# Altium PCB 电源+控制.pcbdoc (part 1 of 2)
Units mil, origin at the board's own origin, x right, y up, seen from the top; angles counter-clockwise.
Board outline 7045 x 4395 mil, 2 copper layers (Top Layer, Bottom Layer); 84 components, 54 nets, 254 pads, 98 vias.
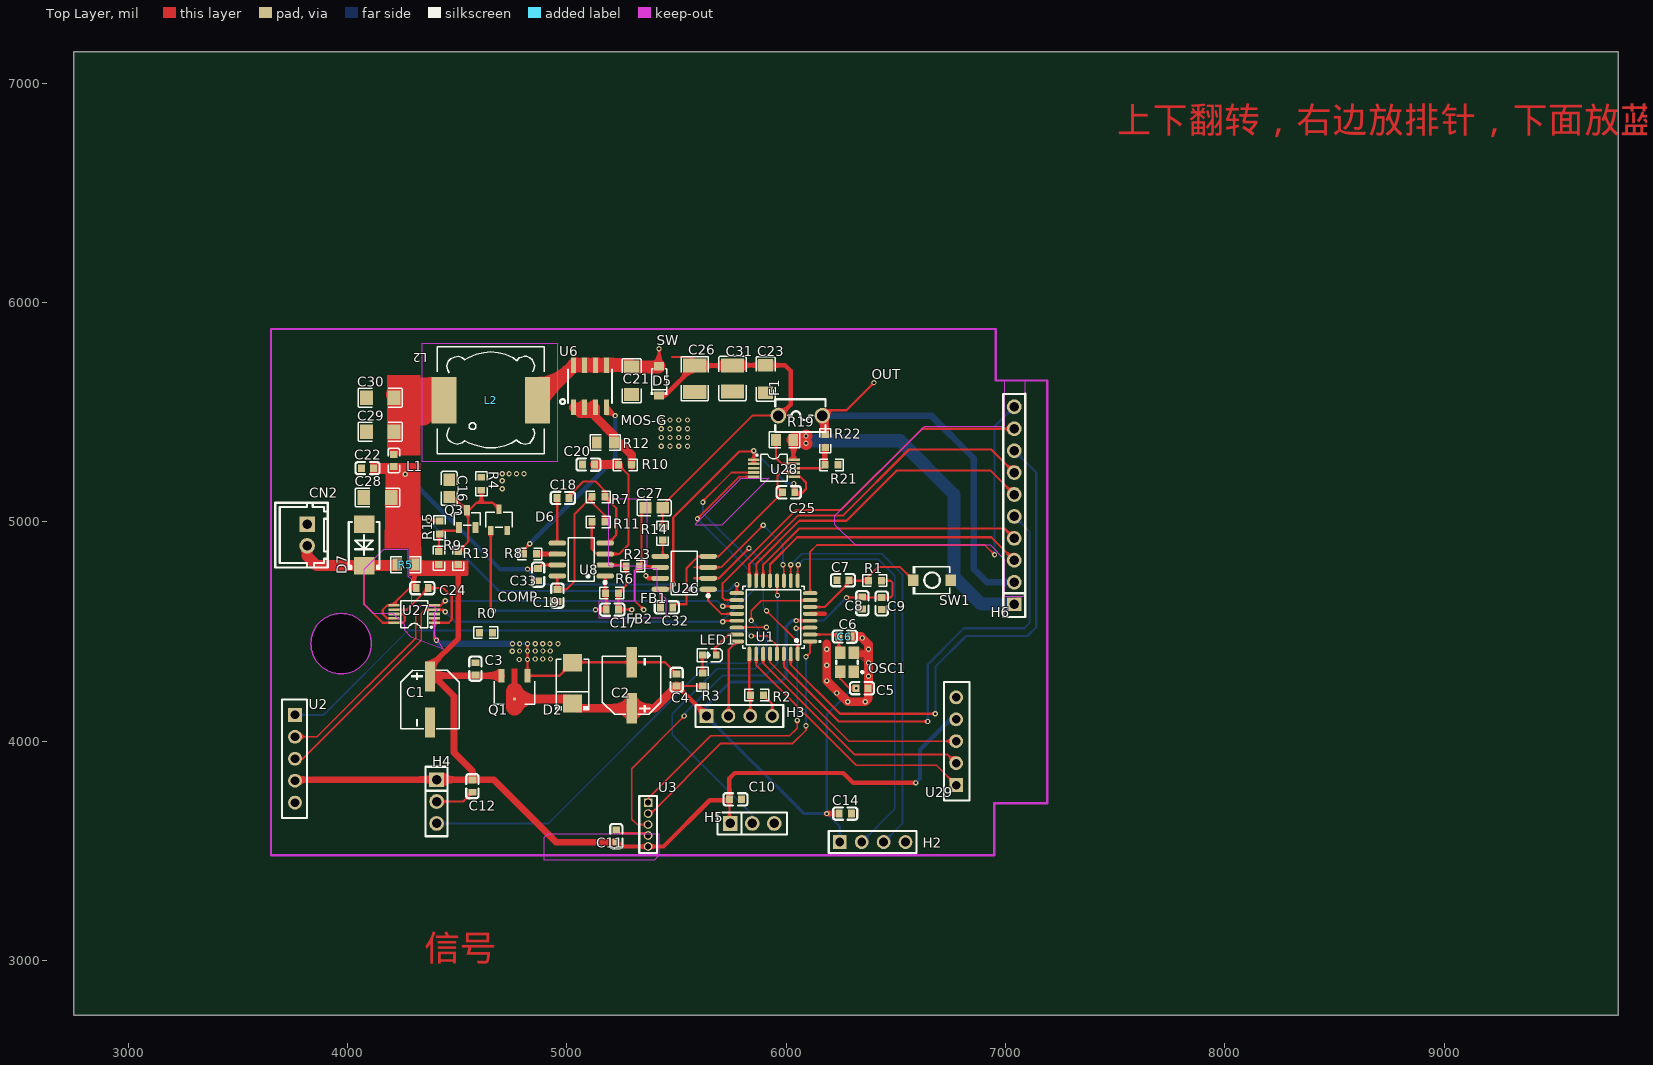
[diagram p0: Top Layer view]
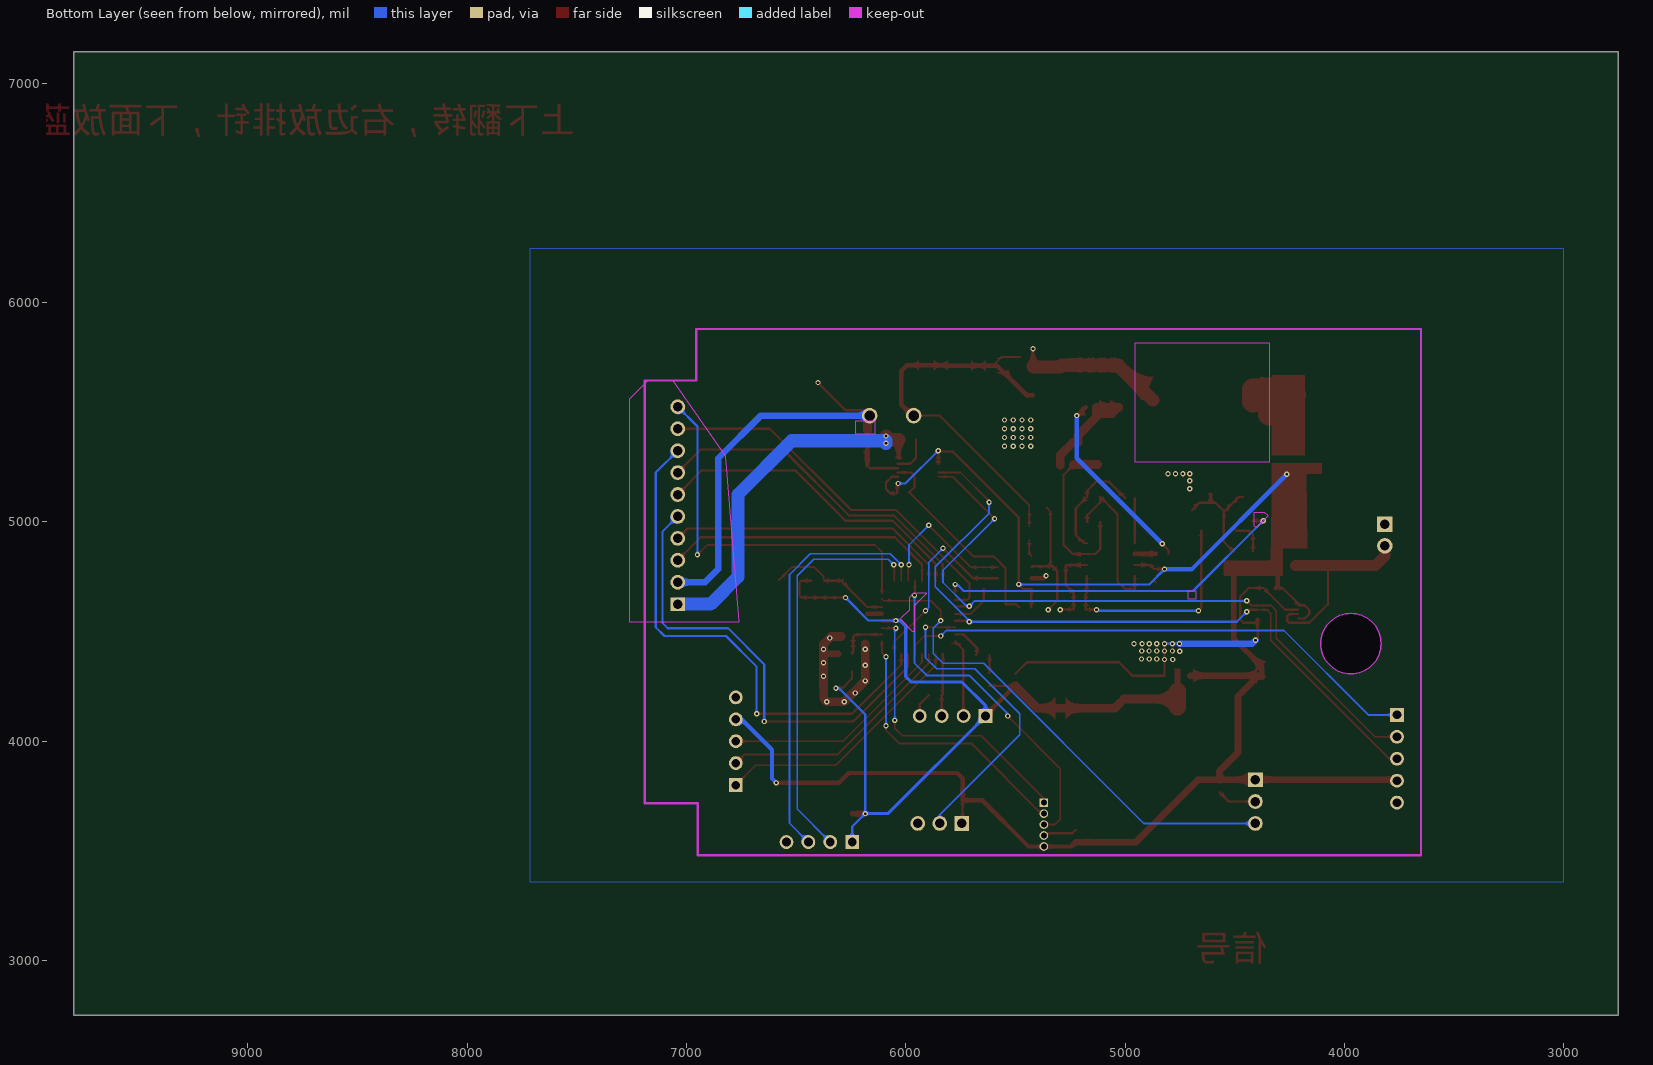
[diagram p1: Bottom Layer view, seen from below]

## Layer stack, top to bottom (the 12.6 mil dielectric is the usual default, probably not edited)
Top Layer: signal copper (thickness not stored)
Dielectric: dielectric 12.6, FR-4, Dk 4.8
Bottom Layer: signal copper (thickness not stored)

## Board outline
9795,2750 2750,2750 2750,7145 9795,7145
cut-out: 4107.8,4445 cw(c3970,4445) 3832.2,4445 cw(c3970,4445)

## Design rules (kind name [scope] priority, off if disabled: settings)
BoardOutlineClearance copperThickness1oz [All] p0: genericclearance=10 ignorepadtopadclearanceinfootprint=FALSE except(0: Arc-SplitContinuation Track-SplitContinuation SMDPad-SplitContinuation THPad-SplitContinuation Via-SplitContinuation Fill-SplitContinuation Poly-SplitContinuation Region-SplitContinuation Text-SplitContinuation; 6: SMDPad-CutoutEdge THPad-CutoutEdge Via-CutoutEdge Fill-CutoutEdge Region-CutoutEdge; 11.8: Track-OutlineEdge SMDPad-OutlineEdge THPad-OutlineEdge Via-OutlineEdge Fill-OutlineEdge Region-OutlineEdge Poly-OutlineEdge Text-OutlineEdge Track-CutoutEdge)
BoardOutlineClearance copperThickness2oz [All] p0: genericclearance=10 ignorepadtopadclearanceinfootprint=FALSE except(0: Arc-SplitContinuation Track-SplitContinuation SMDPad-SplitContinuation THPad-SplitContinuation Via-SplitContinuation Fill-SplitContinuation Poly-SplitContinuation Region-SplitContinuation Text-SplitContinuation; 6: SMDPad-CutoutEdge THPad-CutoutEdge Via-CutoutEdge Fill-CutoutEdge Region-CutoutEdge; 11.8: Track-OutlineEdge SMDPad-OutlineEdge THPad-OutlineEdge Via-OutlineEdge Fill-OutlineEdge Region-OutlineEdge Poly-OutlineEdge Text-OutlineEdge Track-CutoutEdge)
Clearance copperThickness1oz [(InNet('GND') OR InNet('+5V') OR InNet('+3.3V') OR InNet('RADER_RX') OR InNet('OSC_IN') OR InNet('RADER') OR InNet('NRST') OR InNet('LIGHT_ADC') OR InNet('SWITCH6') OR InNet('BLE_TX') OR InNet('BLE_RX') OR InNet('SPI_MOSI') OR InNet('RADER_TX') OR InNet('SWITCH1') OR InNet('SWITCH2') OR InNet('SWITCH4') OR InNet('POWER') OR InNet('SWITCH5') OR InNet('I2C1_SCL') OR InNet('SPI_CS') OR InNet('I2C1_SDA') OR InNet('INFRARED-RAY') OR InNet('LED') OR InNet('SWDIO') OR InNet('SWCLK') OR InNet('CLK') OR InNet('CS') OR InNet('MOSI') OR InNet('DS3231') OR InNet('COLON1') OR InNet('COLON2') OR InNet('$1N3438') OR InNet('$3N2641') OR InNet('$3N2640') OR InNet('VBUS') OR InNet('170_GND') OR InNet('$3N2623') OR InNet('$3N2617') OR InNet('$3N2620') OR InNet('170V') OR InNet('$3N2630') OR InNet('$3N2637') OR InNet('$3N2628') OR InNet('$3N2629') OR InNet('$3N2638') OR InNet('$3N2615') OR InNet('$3N2625') OR InNet('$3N2624') OR InNet('$3N2608') OR InNet('$3N2618') OR InNet('17V') OR InNet('SWITCH3') OR InNet('PGND') OR InNet('SPI_SCK'))] p1: gap=7 ignorepadtopadclearanceinfootprint=FALSE except(4: Track-Track; 6: Track-SMDPad SMDPad-SMDPad Track-THPad SMDPad-THPad THPad-THPad Track-Via SMDPad-Via THPad-Via Via-Via Track-Fill SMDPad-Fill THPad-Fill Via-Fill Fill-Fill SMDPad-Region THPad-Region Via-Region Fill-Region Region-Region Track-Poly SMDPad-Poly THPad-Poly Via-Poly Fill-Poly Poly-Poly Track-Text SMDPad-Text THPad-Text Via-Text Fill-Text Region-Text Poly-Text Text-Text Track-Hole SMDPad-Hole THPad-Hole Via-Hole Fill-Hole Region-Hole Poly-Hole Text-Hole; 11.8: Track-Region Region-Poly Track-Sheet SMDPad-Sheet THPad-Sheet Via-Sheet Fill-Sheet Region-Sheet Poly-Sheet Text-Sheet Sheet-Hole)
Clearance copperThickness2oz [All] p1: gap=7 ignorepadtopadclearanceinfootprint=FALSE except(6: Track-SMDPad SMDPad-SMDPad Track-THPad SMDPad-THPad THPad-THPad Track-Via SMDPad-Via THPad-Via Via-Via Track-Fill SMDPad-Fill THPad-Fill Via-Fill Fill-Fill SMDPad-Region THPad-Region Via-Region Fill-Region Region-Region Track-Poly SMDPad-Poly THPad-Poly Via-Poly Fill-Poly Poly-Poly Track-Text SMDPad-Text THPad-Text Via-Text Fill-Text Region-Text Poly-Text Text-Text Track-Hole SMDPad-Hole THPad-Hole Via-Hole Fill-Hole Region-Hole Poly-Hole Text-Hole; 8: Track-Track; 11.8: Track-Region Region-Poly Track-Sheet SMDPad-Sheet THPad-Sheet Via-Sheet Fill-Sheet Region-Sheet Poly-Sheet Text-Sheet Sheet-Hole)
DiffPairsRouting differentialPair [All] p1: maxuncoupledlength=10 minlimit=6 maxlimit=6 mostfreqgap=6 toplayer_minwidth=5 toplayer_prefwidth=10 toplayer_maxwidth=100 bottomlayer_minwidth=5 bottomlayer_prefwidth=10 bottomlayer_maxwidth=100
PasteMaskExpansion pasteMaskExpansion [All] p1: expansion=0
PlaneConnect innerPlane [All] p1: planeconnectstyle=Relief reliefexpansion=20 reliefentries=4 reliefconductorwidth=10 reliefairgap=10
PolygonConnect copperRegion [All] p1: connectstyle=Relief reliefentries=4 reliefconductorwidth=10 polygonreliefangle="90 Angle" airgapwidth=10
RoutingVias viaSize [All] p1: viastyle="Through Hole" holewidth=12.0078 minholewidth=11.811 maxholewidth=248.0314 width=24.0158 minwidth=19.685 maxwidth=393.7008
SolderMaskExpansion solderMaskExpansion [All] p1: useseparateexpansions=TRUE expansion=2 expansionbottom=2
Width copperThickness1oz [All] p1: maxlimit=100 minlimit=5 preferedwidth=10
Width copperThickness2oz [All] p1: maxlimit=100 minlimit=8 preferedwidth=10

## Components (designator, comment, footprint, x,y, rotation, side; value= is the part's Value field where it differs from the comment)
C1 "RVT220UF10V67RV0037" CAP-SMD_BD6.3-L6.6-W6.6-FD 4375.55,4190 r270 top
C2 "RVT220UF10V67RV0037" CAP-SMD_BD6.3-L6.6-W6.6-FD 5295,4255.09 r90 top
C3 "CC0603KRX7R9BB104" c0603 4582.4,4330.4 r270 top
C4 "CC0603KRX7R9BB104" c0603 5500,4279.79 r270 top
C5 "CC0603KRX7R9BB104" c0603 6346.07,4241.5 r0 top
C6 "CC0603KRX7R9BB104" c0603 6267.31,4477.36 r0 top
C7 "CC0603KRX7R9BB104" c0603 6259.45,4734.1 r0 top
C8 "CC0603KRX7R9BB104" c0603 6346.97,4630 r90 top
C9 "CC0603KRX7R9BB104" c0603 6435.52,4628.44 r90 top
C10 "CC0603KRX7R9BB104" c0603 5768.23,3735 r180 top
C11 "CC0603KRX7R9BB104" c0603 5225,3567.56 r90 top
C12 "CC0603KRX7R9BB104" c0603 4568.73,3794.87 r90 top
C14 "CC0603KRX7R9BB104" c0603 6269.31,3670 r0 top
C16 "CC0805KRX7R9BB104" C0805 4463.04,5152.79 r270 top
C17 "CC0805KRX7R9BB104" c0603 5206.66,4600.41 r180 top
C18 "CC0805KRX7R9BB104" c0603 4981.5,5109.05 r0 top
C19 "CC0805KRX7R9BB104" c0603 4956.38,4664.37 r90 top
C20 "CC0805KRX7R9BB104" c0603 5098.5,5261.61 r0 top
C21 "CC0805KRX7R9BB104" c1206 5295,5643.76 r90 top
C22 "CC0805KRX7R9BB104" c0603 4090.86,5245 r0 top
C23 "CC0805KRX7R9BB104" c1206 5905.99,5651.75 r90 top
C24 "0.1u" c0603 4340.12,4698.19 r180 top
C25 "0.1u" c0603 6011.25,5135 r0 top
C26 "CC0805KRX7R9BB104" c1210 5582.58,5653.03 r90 top
C27 "CC0805KRX7R9BB104" C0805 5397.23,5064.76 r0 top
C28 "CC0805KRX7R9BB104" c1206 4136.14,5111.28 r0 top
C29 "CC0805KRX7R9BB104" c1206 4148.36,5411.28 r0 top
C30 "CC0805KRX7R9BB104" c1206 4148.36,5566.28 r0 top
C31 "CC0805KRX7R9BB104" c1210 5754.88,5653.91 r90 top
C32 "CC0805KRX7R9BB104" c0603 5455,4610.21 r180 top
C33 "CAP_0603" c0603 4868.3,4759.22 r270 top
CN2 "ZX-XH2.54-2PZZ" CONN-TH_2P-P2.50_HX25003-2A 3815,4940 r270 top
COMP "Test-Point" Test-Point-0.5mm 4665.69,4595.29 r0 top
D2 "SMBJ3.3A_C362089" SMB_L4.6-W3.6-LS5.3-RD 5025,4264.72 r90 top
D5 "ES1J_C691230" sod-123_l2.7-w1.6-ls3.6-rd 5420,5643.76 r90 top
D6 "BAT54C,215" SOT-23-3_L2.9-W1.6-P1.90-LS2.8-BR 4690,5009.58 r270 top
D7 "SMBJ5.0A_C726811" SMB_L4.4-W3.6-LS5.3-RD 4075,4895.17 r90 top
F1 "JK250-080U" FUSE-TH_L5.8-W3.8-P5.10-D0.8 6064.4,5485 r0 top
FB1 "Test-Point" Test-Point-0.5mm 5346.22,4600.74 r0 top
FB2 "Test-Point" Test-Point-0.5mm 5297.87,4601.7 r0 top
H2 "排针" SIP-2.54MM-4P-CJT-H8.54 6394.12,3540 r180 top
H3 "排针" SIP-2.54MM-4P-CJT-H8.54 5786.08,4115 r180 top
H4 "PZ254V-11-03P" HDR-TH_3P-P2.54-V-M 4405.36,3725 r270 top
H5 "PZ254V-11-03P" HDR-TH_3P-P2.54-V-M 5845,3625 r0 top
H6 "MH254V-11-10-1196" HDR-TH_10P-P2.54-V-M 7040,5075 r90 top
L1 "PZ3216D101-3R0TF" l0603 4211.06,5280 r90 top
L2 "CXP0630-330M-AG(33uh)" 33uh功率电感 4652.23,5555 r180 top
LED1 "NCD0603R1_C84263" LED0603-RD_RED 5649.3,4392.7 r180 top
MOS-G "Test-Point" Test-Point-0.5mm 5220.34,5484.01 r0 top
OSC1 "OT2EL4C4JI-111OLP-8M" OSC-SMD_4P-L3.2-W2.5-BL-1 6277.13,4360.27 r90 top
OUT "Test-Point" Test-Point-0.5mm 6400.07,5635.31 r0 top
Q1 "AMS1117-3.3V_C5120796" SOT-89-3_L4.5-W2.5-P1.50-LS4.2-BR 4760.78,4245.58 r90 top
Q3 "MMBT5551_C2145" SOT-23-3_L2.9-W1.3-P1.90-LS2.4-BR 4545,5013.67 r270 top
R0 "Res_0603" r0603 4630,4495.1 r0 top
R1 "0805W8F1002T5E_C17414" r0603 6404.02,4732.01 r0 top
R2 "0805W8F1002T5E_C17414" r0603 5865.74,4210 r180 top
R3 "0805W8F1002T5E_C17414" r0603 5618.82,4282.01 r90 top
R4 "0805W8F1002T5E_C17414" r0603 4609.8,5174.08 r270 top
R5 "10mΩ" R0805 4265,4805.25 r180 top
R6 "0805W8F1002T5E_C17414" r0603 5204.43,4675.24 r180 top
R7 "0805W8F1002T5E_C17414" r0603 5143.03,5114.29 r180 top
R8 "0805W8F1002T5E_C17414" r0603 4831.07,4854.37 r0 top
R9 "0805W8F1002T5E_C17414" r0603 4416.26,4834.91 r270 top
R10 "0805W8F1002T5E_C17414" r0603 5265.34,5260 r180 top
R11 "0805W8F1002T5E_C17414" r0603 5143.03,5000.02 r0 top
R12 "RL10FTNR160" R0805 5174.73,5362.41 r0 top
R13 "0805W8F1002T5E_C17414" r0603 4504.37,4834.91 r270 top
R14 "0805W8F1002T5E_C17414" r0603 5436.6,4948.08 r90 top
R15 "0805W8F1002T5E_C17414" r0603 4419.46,4973.68 r90 top
R19 "100mΩ" R0805 5992.89,5374.48 r0 top
R21 "0805W8F1002T5E_C17414" r0603 6206.39,5260 r0 top
R22 "0805W8F1002T5E_C17414" r0603 6177.87,5370 r270 top
R23 "0805W8F1002T5E_C17414" r0603 5300,4798.12 r180 top
SW "Test-Point" Test-Point-0.5mm 5420,5790 r0 top
SW1 "TS-1088R-02026" SW-SMD_L3.9-W3.0-P4.45 6665,4734.21 r180 top
U1 "STM32G070KBT6" LQFP-32_L7.0-W7.0-P0.80-LS9.0-BL 5941.89,4565 r90 top
U2 "2.54mm1*5" 2.54mm1*5 3760,3920.06 r270 top
U3 "FH1.27-01-5PZD" HDR-TH_5P-P1.27-V-M 5370,3620 r270 top
U6 "FDS2672" SO-8_L4.9-W3.9-P1.27-LS6.0-BL 5105,5618.79 r0 top
U8 "UCC3803D" SOIC-8_L4.9-W3.9-P1.27-LS6.0-BL 5065,4828.56 r90 top
U26 "MCP41010T-I/SN" SOIC-8_L4.9-W3.9-P1.27-LS6.0-BL 5535,4767.96 r90 top
U27 "INA220AIDGSR" VSSOP-10_L3.0-W3.0-P0.50-LS4.9-BL 4303.58,4580 r90 top
U28 "INA220AIDGSR" VSSOP-10_L3.0-W3.0-P0.50-LS4.9-BL 5944.27,5245 r270 top
U29 "2.54mm1*5" 2.54mm1*5 6775,4000 r90 top

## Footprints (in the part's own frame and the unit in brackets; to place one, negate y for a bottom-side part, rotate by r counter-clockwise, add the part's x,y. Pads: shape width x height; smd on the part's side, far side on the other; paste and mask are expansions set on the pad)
2.54mm1*5 [mm]
  rect 1.6x1.6 hole 1: 1(-5.08,0)
  round 1.6 hole 1: 2(-2.54,0) 3(0,0) 4(2.54,0) 5(5.08,0)
  silkscreen extent -6.86,-1.52 6.86,1.4
33uh功率电感 [mm]
  rect 2.9x5.4 smd: 1(5.4,0) 2(-5.4,0)
  silkscreen extent -6.2,-6.2 6.2,6.2
c0603 [mm]
  rect 0.8x0.9 smd: 1(-0.7,0) 2(0.7,0)
  silkscreen extent -1.41,-0.71 1.39,0.72
C0805 [mm]
  rect 1.41x1.35 smd: 1(-1,0) 2(1,0)
  silkscreen extent -1.96,-0.9 1.96,0.9
c1206 [mm]
  rect 1.485x1.728 smd: 1(-1.593,0) 2(1.593,0)
  silkscreen extent -2.56,-1.09 2.56,1.09
c1210 [mm]
  rect 1.635x2.7 smd: 1(-1.517,0) 2(1.517,0)
  silkscreen extent -2.56,-1.58 2.56,1.58
CAP-SMD_BD6.3-L6.6-W6.6-FD [mm]
  rect 3.5x1.2 smd: 1(-2.67,0) 2(2.67,0)
  silkscreen extent -3.38,-3.38 3.38,3.38
CONN-TH_2P-P2.50_HX25003-2A [mm]
  rect 1.8x1.8 hole 1.1: 1(-1.25,0)
  round 1.8 hole 1.1: 2(1.25,0)
  silkscreen extent -3.75,-3.7 3.75,2.41
FUSE-TH_L5.8-W3.8-P5.10-D0.8 [mm]
  round 1.8 hole 1.2: 1(-2.55,0) 2(2.55,0)
  silkscreen extent -2.9,-1.9 2.9,1.9
HDR-TH_3P-P2.54-V-M [mm]
  rect 1.7x1.7 hole 1.1: 1(-2.54,0)
  round 1.7 hole 1.1: 2(0,0) 3(2.54,0)
  silkscreen extent -4.02,-1.27 4.02,1.27
HDR-TH_5P-P1.27-V-M [mm]
  rect 1x1 hole 0.7: 1(-2.54,0)
  round 1 hole 0.7: 2(-1.27,0) 3(0,0) 4(1.27,0) 5(2.54,0)
  silkscreen extent -3.3,-1.02 3.3,1.02
HDR-TH_10P-P2.54-V-M [mm]
  rect 1.575x1.7 hole 1.1: 1(-11.43,0)
  round 1.7 hole 1.1: 2(-8.89,0) 3(-6.35,0) 4(-3.81,0) 5(-1.27,0) 6(1.27,0) 7(3.81,0) 8(6.35,0) 9(8.89,0) 10(11.43,0)
  silkscreen extent -12.9,-1.27 12.95,1.27
l0603 [mm]
  rect 0.8x0.864 smd: 1(-0.7,0) 2(0.7,0)
  silkscreen extent -1.42,-0.65 1.41,0.67
LED0603-RD_RED [mm]
  rect 0.8x0.8 smd: 1(-0.8,-0.003) 2(0.8,0.003)
  silkscreen extent -1.49,-0.75 1.39,0.76
LQFP-32_L7.0-W7.0-P0.80-LS9.0-BL [mm]
  oval 0.448x1.684 smd: 1(-2.8,-4.242) 2(-2,-4.242) 3(-1.2,-4.242) 4(-0.4,-4.242) 5(0.4,-4.242) 6(1.2,-4.242) 7(2,-4.242) 8(2.8,-4.242) 17(2.8,4.242) 18(2,4.242) 19(1.2,4.242) 20(0.4,4.242) 21(-0.4,4.242) 22(-1.2,4.242) 23(-2,4.242) 24(-2.8,4.242)
  oval 1.684x0.448 smd: 9(4.242,-2.8) 10(4.242,-2) 11(4.242,-1.2) 12(4.242,-0.4) 13(4.242,0.4) 14(4.242,1.2) 15(4.242,2) 16(4.242,2.8) 25(-4.242,2.8) 26(-4.242,2) 27(-4.242,1.2) 28(-4.242,0.4) 29(-4.242,-0.4) 30(-4.242,-1.2) 31(-4.242,-2) 32(-4.242,-2.8)
  silkscreen extent -3.58,-5.48 3.58,3.58
OSC-SMD_4P-L3.2-W2.5-BL-1 [mm]
  rect 1.4x1.2 smd: 1(-1.1,-0.8) 2(1.1,-0.8) 3(1.1,0.8) 4(-1.1,0.8)
  silkscreen extent -1.27,-1.91 0.17,1.25
r0603 [mil]
  rect 31.75x34.02 smd: 1(-29.66,0) 2(29.66,0)
  silkscreen extent -55,-26 55,26
R0805 [mm]
  rect 1.133x1.377 smd: 1(-1,0) 2(1,0)
  silkscreen extent -1.76,-0.92 1.76,0.92
SIP-2.54MM-4P-CJT-H8.54 [mm]
  rect 1.6x1.6 hole 1.02: 1(3.81,0)
  round 1.6 hole 1.02: 2(1.27,0) 3(-1.27,0) 4(-3.81,0)
  silkscreen extent -5.08,-1.27 5.08,1.27
SMB_L4.4-W3.6-LS5.3-RD [mm]
  rect 2x2.4 smd: 1(-2.4,0) 2(2.4,0)
  silkscreen extent -2.76,-1.78 2.67,1.78
SMB_L4.6-W3.6-LS5.3-RD [mil]
  rect 80.61x86.31 smd: 1(-92.94,0) 2(92.94,0)
  silkscreen extent -123,-77 108,77
SO-8_L4.9-W3.9-P1.27-LS6.0-BL [mm]
  rect 0.6x1.8 smd: 1(-1.905,-2.45) 2(-0.635,-2.45) 3(0.635,-2.45) 4(1.905,-2.45) 5(1.905,2.45) 6(0.635,2.45) 7(-0.635,2.45) 8(-1.905,2.45)
  silkscreen extent -3.46,-2.06 2.54,1.91
sod-123_l2.7-w1.6-ls3.6-rd [mm]
  rect 0.95x1.15 smd: 1(-1.692,0) 2(1.692,0)
  silkscreen extent -1.63,-0.94 1.41,0.94
SOIC-8_L4.9-W3.9-P1.27-LS6.0-BL [mm]
  oval 0.588x2.045 smd: 1(-1.905,-2.772) 2(-0.635,-2.772) 3(0.635,-2.772) 4(1.905,-2.772) 5(1.905,2.772) 6(0.635,2.772) 7(-0.635,2.772) 8(-1.905,2.772)
  silkscreen extent -2.8,-2.92 2.53,1.52
SOT-23-3_L2.9-W1.3-P1.90-LS2.4-BR [mm]
  rect 1.25x0.7 smd: 1(1,-0.95) 2(1,0.95) 3(-1,0)
  silkscreen extent -0.73,-1.53 0.73,1.53
SOT-23-3_L2.9-W1.6-P1.90-LS2.8-BR [mm]
  rect 1.07x0.6 smd: 1(1.235,-0.95) 2(1.235,0.95) 3(-1.235,0)
  silkscreen extent -0.88,-1.54 0.88,1.54
SOT-89-3_L4.5-W2.5-P1.50-LS4.2-BR [mm]
  rect 1.575x0.672 smd: 1(1.356,-1.5) 3(1.356,1.5)
  round 0.38 smd: 2(-1.356,0)
  Top Layer region: -2.283,0.95 -0.429,0.95 -0.384,0.949 -0.34,0.946 -0.296,0.94 -0.252,0.933 -0.208,0.924 -0.165,0.912 -0.123,0.899 -0.081,0.884 -0.04,0.866 0,0.847 0.04,0.826 0.078,0.803 0.115,0.779 0.151,0.752 0.185,0.724 0.219,0.695 0.251,0.664 0.281,0.631 0.31,0.597 0.337,0.562 0.362,0.525 0.386,0.488 0.408,0.449 0.428,0.409 0.447,0.33 2.144,0.33 2.144,-0.33 0.447,-0.33 0.428,-0.409 0.408,-0.449 0.386,-0.488 0.362,-0.526 0.337,-0.562 0.31,-0.597 0.281,-0.631 0.251,-0.664 0.219,-0.695 0.185,-0.725 0.151,-0.753 0.115,-0.779 0.078,-0.804 0.04,-0.827 0,-0.848 -0.04,-0.867 -0.081,-0.884 -0.123,-0.899 -0.165,-0.913 -0.208,-0.924 -0.252,-0.934 -0.296,-0.941 -0.34,-0.946 -0.384,-0.949 -0.429,-0.95 -2.283,-0.95 -2.328,-0.949 -2.372,-0.946 -2.416,-0.941 -2.46,-0.934 -2.504,-0.924 -2.547,-0.913 -2.589,-0.899 -2.631,-0.884 -2.672,-0.867 -2.713,-0.848 -2.752,-0.827 -2.79,-0.804 -2.827,-0.779 -2.863,-0.753 -2.898,-0.725 -2.931,-0.695 -2.963,-0.664 -2.993,-0.631 -3.022,-0.597 -3.049,-0.562 -3.075,-0.526 -3.098,-0.488 -3.12,-0.449 -3.141,-0.409 -3.159,-0.369 -3.175,-0.327 -3.189,-0.285 -3.202,-0.242 -3.212,-0.199 -3.22,-0.155 -3.227,-0.111 -3.231,-0.067 -3.233,-0.022 -3.233,0.022 -3.231,0.067 -3.227,0.111 -3.22,0.155 -3.212,0.199 -3.202,0.242 -3.189,0.285 -3.175,0.327 -3.159,0.369 -3.141,0.409 -3.12,0.449 -3.098,0.488 -3.075,0.525 -3.049,0.562 -3.022,0.597 -2.993,0.631 -2.963,0.664 -2.931,0.695 -2.898,0.724 -2.863,0.752 -2.827,0.779 -2.79,0.803 -2.752,0.826 -2.713,0.847 -2.672,0.866 -2.631,0.884 -2.589,0.899 -2.547,0.912 -2.504,0.924 -2.46,0.933 -2.416,0.94 -2.372,0.946 -2.328,0.949
  silkscreen extent -1.95,-2.33 0.7,2.33
SW-SMD_L3.9-W3.0-P4.45 [mm]
  rect 1.23x1.36 smd: 1(-2.185,0) 2(2.185,0)
  silkscreen extent -2.03,-1.62 2.25,1.62
Test-Point-0.5mm [mm]
  round 0.5 smd: 1(0,0)
VSSOP-10_L3.0-W3.0-P0.50-LS4.9-BL [mm]
  rect 0.3x1.3 smd: 1(-1,-2.35) 2(-0.5,-2.35) 3(0,-2.35) 4(0.5,-2.35) 5(1,-2.35) 6(1,2.35) 7(0.5,2.35) 8(0,2.35) 9(-0.5,2.35) 10(-1,2.35)
  silkscreen extent -1.62,-2.08 1.52,1.54

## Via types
v1: diameter 24.02, hole 12.01, Top Layer to Bottom Layer, 98 vias

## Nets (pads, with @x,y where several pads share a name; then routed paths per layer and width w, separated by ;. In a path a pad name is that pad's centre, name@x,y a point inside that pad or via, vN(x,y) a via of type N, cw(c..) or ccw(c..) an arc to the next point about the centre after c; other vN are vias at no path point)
17V: R21.1 R22.2 U28.8 | length 232.9
  Top Layer w10: U28.8@6036.79,5244.99 6161.73,5244.99 R21.1@6175.69,5258.97 ; R21.1@6176.27,5259.54 R21.1@6176.73,5260
  Top Layer w20: R22.2@6175,5346.78 6175,5340.45 6175.58,5339.87 R21.1@6175.58,5260.24 ; R21.1@6175.69,5258.97 R21.1@6176.27,5259.54
170_GND: H6.1 R19.2 U28.10 | length 1662.7
  Top Layer w15: U28.10@6032.26,5288.9 R19.2@6032.26,5374.48
  Top Layer w60: R19.2@6032.26,5374.48 6072.34,5374.48 v1(6090,5392.14) ; 6073.95,5374.48 v1(6090,5358.43)
  Bottom Layer w60: v1(6090,5358.43) 6090,5369.3 6090.7,5370 6520,5370 6765,5125 6765,4750 6890,4625 H6.1@7040,4625
170V: F1.2 H6.2 OUT.1 R22.1 | length 1856.3
  Top Layer w10: F1.2@6165,5509.6 6274.36,5509.6 v1(6400.07,5635.31)
  Top Layer w40: 6175,5416.1 F1.2@6175,5499.6
  Bottom Layer w30: F1.2@6165,5485 6660,5485 6855,5290 6855,4785 6915,4725 H6.2@7040,4725
$1N3438: LED1.2 R3.2 | length 81.3
  Top Layer w10: LED1.2@5617.83,4392.56 5617.83,4312.67 R3.2@5618.82,4311.67
$3N2608: Q3.1 R9.1 R15.1 | length 181.5
  Top Layer w10: R9.1@4416.26,4864.57 4416.26,4940.81 R15.1@4419.46,4944.02 4435.44,4960 4493.3,4960 Q3.1@4507.6,4974.3
$3N2615: C18.2 R7.1 U8.4 | length 512.7
  Top Layer w10: C18.2@4999.06,5109.05 5075,5185 5130,5185 5172.69,5142.31 R7.1@5172.69,5114.29 5225,5061.98 5225,4940 5188.56,4903.56 U8.4@5174.15,4903.56
$3N2617: MOS-G.1 R8.1 U6.4 | length 859.5
  Top Layer w10: R8.1@4801.41,4854.37 4801.41,4871.41 v1(4830,4900)
  Top Layer w20: U6.4@5180,5522.33 5217.33,5485 v1(5220,5485)
  Bottom Layer w20: v1(4830,4900) 5220,5290 v1(5220,5485)
$3N2618: R8.2 U8.6 | length 95.5
  Top Layer w20: R8.2@4860.73,4854.37 4955.04,4854.37 U8.6@4955.85,4853.56
$3N2620: C21.2 D5.2 L2.2 SW.1 U6.5 U6.6 U6.7 U6.8 | length 699.6
  Top Layer w10: D5.2@5420,5710.39 v1(5420,5790)
  Top Layer w60: L2.2@4872.6,5555.76 5030,5713.16 U6.8@5030,5715.25 U6.7@5080,5715.25 U6.6@5130,5715.25 U6.5@5180,5715.25 5286.21,5715.25 C21.2@5295,5706.46 5416.07,5706.46 D5.2@5420,5710.39
$3N2623: R10.1 R12.2 U6.1 U6.2 U6.3 | length 564.4
  Top Layer w40: U6.1@5030,5522.33 U6.1@5032.67,5522.33 ; R10.1@5295,5260 5295,5305 5237.59,5362.41 R12.2@5214.1,5362.41 5214.1,5395.29 5130,5479.4 U6.3@5130,5522.33 ; U6.1@5032.67,5522.33 5060,5495 5102.67,5495 U6.3@5130,5522.33 ; U6.1@5032.67,5522.33 U6.2@5080,5522.33 U6.3@5130,5522.33
$3N2624: C20.2 R10.2 R11.1 U8.3 | length 810.4
  Top Layer w10: R11.1@5113.37,5000.02 5113.37,4876.63 5136.44,4853.56 U8.3@5174.15,4853.56 5238.56,4853.56 5280,4895 5280,5215.68 R10.2@5235.68,5260
  Top Layer w40: C20.2@5126.06,5261.61 5234.07,5261.61 R10.2@5235.68,5260
$3N2625: C19.2 R7.2 R11.2 U8.8 | length 711.8
  Top Layer w10: U8.8@4955.85,4753.56 4955.85,4692.45 C19.2@4956.38,4691.93 4996.93,4691.93 5035,4730 5035,5035.93 R7.2@5113.37,5114.29 5113.37,5090.19 5172.69,5030.87 R11.2@5172.69,5000.02
$3N2628: C16.2 D6.3 Q3.3 R4.2 R13.1 | length 536.2
  Top Layer w10: C16.2@4463.04,5113.42 4481.58,5113.42 Q3.3@4550,5045 ; R13.1@4504.37,4864.57 4550,4910.2 Q3.3@4550,5045 ; R4.2@4609.8,5129.42 4609.8,5087.85 ; D6.3@4695,5053.21 D6.3@4690,5058.21 4660.36,5087.85 4609.8,5087.85 ; Q3.3@4550,5045 4550,5050 4587.85,5087.85 4609.8,5087.85
$3N2629: C17.2 COMP.1 D6.1 R6.2 U8.1 | length 1042.6
  Top Layer w10: D6.1@4652.6,4960.96 4652.6,4607.4 v1(4665,4595) ; v1(5130,4600) 5178.69,4600 C17.2@5179.1,4600.41 5179.1,4670.91 R6.2@5174.77,4675.24 5174.77,4752.94 U8.1@5174.15,4753.56
  Bottom Layer w10: v1(4665,4595) 5125,4595 v1(5130,4600)
$3N2630: C29.2 C30.2 L1.2 L2.1 | length 741.8
  Top Layer w40: 4211.06,5325 C29.2@4211.06,5411.28 C30.2@4211.06,5566.28
  Top Layer w80: 4343.14,5490 4343.14,5543.14 4350,5550 L2.1@4417.4,5550
  Top Layer w100: C30.2@4225.18,5580.3 4250.26,5605.22 4417.4,5604.66 L2.1@4417.4,5550 ; 4230,5490 4343.14,5490
$3N2637: C23.2 C26.2 C27.2 C31.2 D5.1 F1.1 R14.2 | length 1828.7
  Top Layer w8: R14.2@5436.6,4977.74 C27.2@5436.6,5064.76 5436.6,5076.6 5845,5485 F1.1@5964,5485 ; 5477.98,5751.78 5563.38,5751.78 C26.2@5602.57,5712.59
  Top Layer w20: D5.1@5420,5577.13 5448.28,5577.13 5583.74,5712.59 5602.57,5712.59 5604.41,5712.59 5805.82,5712.59 5807.69,5714.45 C23.2@5905.99,5714.45 5994.25,5714.45 6020,5688.7 6020,5535 5979.82,5494.82 F1.1@5969.64,5505
$3N2638: C17.1 FB2.1 R6.1 R23.2 U8.2 | length 375.4
  Top Layer w10: U8.2@5174.15,4803.56 5264.91,4803.56 R23.2@5270.34,4798.12 5270.34,4711.49 R6.1@5234.09,4675.24 5234.22,4675.11 C17.1@5234.22,4600.41 5296.59,4600.41 FB2.1@5297.87,4601.7
  other v1: 5295,4600
$3N2640: R14.1 U26.5 | length 79.9
  Top Layer w8: U26.5@5425.85,4842.96 5436.6,4853.71 R14.1@5436.6,4918.42
$3N2641: C27.1 FB1.1 R23.1 U26.6 | length 600.5
  Top Layer w8: R23.1@5329.66,4798.12 5340,4808.46 5340,5046.9 C27.1@5357.86,5064.76
  Top Layer w10: v1(5350,4600) 5308.78,4641.22 5308.78,4776.11 5329.66,4796.99 R23.1@5329.66,4798.12 5420.69,4798.12 U26.6@5425.85,4792.96
+3.3V: C2.1 C4.2 C5.1 C8.2 C9.2 C14.1 D2.1 H2.1 H3.1 OSC1.4 Q1.2 R1.2 R3.1 U1.4 | length 4231.5
  Top Layer w10: C4.2@5500,4252.23 5500.13,4252.35 R3.1@5618.82,4252.35 ; OSC1.4@6245.63,4316.96 6245.63,4284.37 6288.5,4241.5 v1(6318.51,4241.5) ; v1(6275,4655) 6475,4655 6485,4665 6485,4722.01 6475,4732.01 R1.2@6433.68,4732.01
  Top Layer w15: v1(6045,4550) 6108.15,4550 U1.4@6108.9,4549.25
  Top Layer w20: C4.2@5500,4250 5505,4250 5636.08,4118.92 H3.1@5636.08,4115
  Top Layer w25: v1(6185,3670) C14.1@6241.76,3670
  Top Layer w40: Q1.2@4760.79,4192.19 5004.6,4192.19 D2.1@5025,4171.78 5046.81,4149.97 C2.1@5295,4149.97 5399.97,4149.97 5500,4250 C4.2@5500,4252.23
  Bottom Layer w10: v1(6045,4550) 6170,4550 v1(6275,4655) ; H2.1@6244.12,3540 6244.12,3610.88 v1(6185,3670) 6185,4122.13 6304.37,4241.5 v1(6318.51,4241.5)
  Bottom Layer w15: v1(6045,4550) 6025,4550 6000,4525 6000,4295 5975,4270 5745,4270 5636.08,4161.08 H3.1@5636.08,4115 6081.08,3670 v1(6185,3670)
+5V: C1.1 C3.2 C10.2 C11.1 C12.2 C22.2 C24.2 C25.2 C28.2 C32.2 C33.1 H4.1 H5.1 L1.1 Q1.3 R5.1 R9.2 R13.2 U2.4 U3.5 U8.7 U26.8 U27.6 U27.9 U28.1 U28.2 U28.6 U29.4 | length 9356.3
  Top Layer w10: U27.9@4211.06,4560.31 4179.69,4560.31 4160,4580 4160,4598.89 4180.47,4619.36 U27.6@4202.48,4619.36 ; U27.6@4211.06,4619.36 U27.6@4202.48,4619.36 ; C24.2@4312.56,4698.19 4281.31,4698.19 U27.6@4202.48,4619.36 ; v1(4820,4785) 4866.53,4785 C33.1@4868.3,4786.78 4885.08,4803.56 U8.7@4955.85,4803.56 ; C32.2@5427.44,4610.21 5427.44,4691.37 U26.8@5425.85,4692.96 5462.96,4692.96 v1(5485,4715) 5485,5020 5786.75,5321.75 v1@5851.75,5321.75 ; C10.2@5740.67,3730.67 5740.67,3629.33 H5.1@5745,3625 ; U28.2@5851.75,5264.69 U28.1@5851.75,5284.36 v1@5851.75,5321.75 ; v1(5851.75,5325) v1@5851.75,5321.75 ; v1(6035,5175) 6038.81,5171.19 C25.2@6038.81,5135 6043.81,5130 6070,5130 6090,5150 6090,5180 6064.36,5205.64 U28.6@6036.79,5205.64
  Top Layer w20: R5.1@4304.37,4805.25 4304.37,4706.38 C24.2@4312.56,4698.19 ; C11.1@5225,3540 5245,3520 U3.5@5370,3520 5440,3520 5650.67,3730.67 5740.67,3730.67 5740.67,3830.67 5765,3855 6260,3855 6305,3810 v1(6590,3810)
  Top Layer w25: L1.1@4211.06,5252.44 4227.56,5252.44 v1(4262.04,5217.96) ; C1.1@4375.55,4295.12 4375.55,4340.05 4504.37,4468.86 R13.2@4504.37,4805.25
  Top Layer w30: U2.4@3760,3820.06 3764.94,3825 H4.1@4405.36,3825 4566.15,3825 C12.2@4568.73,3822.43 ; R5.1@4304.37,4805.25 R9.2@4416.26,4805.25 R13.2@4504.37,4805.25 ; Q1.3@4701.73,4298.98 4379.41,4298.98 C1.1@4375.55,4295.12 4394.88,4295.12 4485,4205 4485,3948.58 4568.73,3864.85 C12.2@4568.73,3822.43 ; C11.1@5225,3540 4950,3540 4665,3825 4571.3,3825 C12.2@4568.73,3822.43
  Top Layer w40: 4135,5245 L1.1@4205,5245 ; L1.1@4210,5240 4210,5130.1 4198.84,5118.94 C28.2@4198.84,5111.28 4198.84,4991.16 4304.37,4885.63 R5.1@4304.37,4805.25
  Bottom Layer w10: v1(4820,4785) 4890,4715 v1(5485,4715) ; v1(5851.75,5325) 6001.75,5175 v1(6035,5175)
  Bottom Layer w20: v1(4262.04,5217.96) 4695,4785 v1(4820,4785) ; v1(6590,3810) 6610,3830 6610,3961.21 6748.79,4100 U29.4@6775,4100
BLE_RX: H2.3 U1.10 | length 1898.9
  Top Layer w8: v1(6020,4805) 6020.63,4804.37 U1.10@6020.63,4732.01
  Bottom Layer w8: v1(6020,4805) 6070,4855 6435,4855 6530,4760 6530,3625.88 H2.3@6444.12,3540
BLE_TX: H2.2 U1.9 | length 1833.1
  Top Layer w8: U1.9@6052.13,4732.01 6052.13,4802.13 v1(6055,4805)
  Bottom Layer w8: v1(6055,4805) 6080,4830 6420,4830 6495,4755 6495,3690.88 H2.2@6344.12,3540
CLK: U1.28 U29.3 | length 1036.1
  Top Layer w8: U1.28@5926.14,4397.99 5926.14,4359.84 6285.98,4000 U29.3@6775,4000
COLON1: H6.5 U1.30 | length 2134.6
  Top Layer w10: U1.30@5989.13,4397.99 5989.13,4340.87 6240,4090 v1(6645,4090)
  Bottom Layer w10: v1(6645,4090) 6645,4350 6810,4515 7085,4515 7110,4540 7110,4955 H6.5@7040,5025
COLON2: H6.8 U1.31 | length 2396.9
  Top Layer w10: U1.31@6020.63,4397.99 6020.63,4349.37 6245,4125 v1(6680,4125)
  Bottom Layer w10: v1(6680,4125) 6680,4340 6820,4480 7100,4480 7140,4520 7140,5225 H6.8@7040,5325
CS: U1.27 U29.2 | length 1111.6
  Top Layer w8: U1.27@5894.65,4397.99 5894.65,4355.35 6310,3940 6735,3940 U29.2@6775,3900
DS3231: U1.29 U2.1 | length 2424.5
  Top Layer w8: v1(5840,4480) 5915,4480 5957.64,4437.36 U1.29@5957.64,4397.99
  Bottom Layer w8: U2.1@3760,4120.06 3890.06,4120.06 4275,4505 5815,4505 v1(5840,4480)
GND: C2.2 C4.1 C5.2 C6.2 C7.1 C8.1 C9.1 C10.1 C11.2 C12.1 C14.2 C18.1 C19.1 C24.1 C25.1 C32.1 C33.2 D2.2 H2.4 H3.4 H4.2 H5.3 OSC1.2 Q1.1 R0.2 R2.1 SW1.1 U1.5 U2.5 U3.4 U8.5 U26.4 U27.1 U27.2 U27.7 U28.7 U29.5 | length 4437.3
  Top Layer w10: U27.7@4211.06,4599.69 4269.17,4599.69 C24.1@4367.68,4698.19 4436.81,4698.19 4475,4660 4475,4555 4460.64,4540.64 U27.1@4396.1,4540.64 ; U27.2@4396.1,4560.31 U27.1@4396.1,4540.64 ; v1(4405,4460) 4395.25,4466.5 U27.1@4396.1,4540.64 ; H4.2@4405.36,3725 4526.42,3725 C12.1@4568.73,3767.31 ; v1(4820,4445) 4819.84,4444.84 v1(4819.84,4411.54) v1(4819.84,4372.96) Q1.1@4819.84,4298.98 4966.31,4298.98 D2.2@5025,4357.66 5027.55,4360.21 C2.2@5295,4360.21 5447.13,4360.21 C4.1@5500,4307.35 ; C33.2@4861.65,4725 C33.2@4868.3,4731.66 ; C18.1@4953.94,5109.05 4955.85,5107.14 U8.5@4955.85,4903.56 ; C11.2@5225,3595.12 5240.12,3580 5360,3580 U3.4@5370,3570 ; C32.1@5482.56,4610.21 5497.35,4625 5545,4625 5545,4789.07 5598.89,4842.96 U26.4@5644.15,4842.96 5691.65,4842.96 C25.1@5983.69,5135 5960,5158.69 5960,5210 5975.31,5225.31 U28.7@6036.79,5225.31 ; R2.1@5895.4,4210 5936.08,4169.32 H3.4@5936.08,4115
  Top Layer w20: U1.5@6108.9,4580.75 6175,4580.75
  Top Layer w30: OSC1.2@6308.63,4398.31 6375,4398.31
  Top Layer w40: 6185,4445 v1(6185,4419.36) v1(6185,4346.52) v1(6185,4275) v1(6280,4180) v1(6360,4180) 6373.63,4193.63 C5.2@6373.63,4241.5 6375,4242.87 v1(6375,4296.82) v1(6375,4357.66) 6375,4398.31 v1(6375,4419.36) 6375,4442.7 6340.34,4477.36 C6.2@6294.87,4477.36
  Bottom Layer w10: v1(4751.43,4445) v1(4783.98,4445) v1(4820,4445)
  Bottom Layer w30: v1(4405,4460) 4420,4445 v1(4751.43,4445)
  other v1: 6230,4220 4782.54,4372.96 4855,4375 4890,4375 4925,4375 4750,4410 4783.98,4411.54 4855.98,4411.54 4890.41,4411.54 4924.21,4411.54 4855,4445 4889.16,4445 4922.33,4445 4959.27,4445 6347,4470.7
I2C1_SCL: U1.19 U2.2 U27.5 U28.5 | length 3245.8
  Top Layer w8: U2.2@3760,4020.06 3860.06,4020.06 4310,4470 4310,4595 4334.38,4619.38 U27.5@4396.1,4619.38 ; v1(5595,5015) 5785.62,5205.62 U28.5@5851.75,5205.62
  Top Layer w10: U27.5@4396.1,4619.38 4424.38,4619.38 v1(4445,4640) ; v1(5710,4615) 5772.12,4615 U1.19@5774.88,4612.24
  Bottom Layer w8: v1(5595,5015) 5830,4780 5830,4723.69 5721.31,4615 v1(5710,4615)
  Bottom Layer w10: v1(4445,4640) 5685,4640 v1(5710,4615)
I2C1_SDA: U1.21 U2.3 U27.4 U28.4 | length 3394
  Top Layer w8: U2.3@3760,3920.06 3795.06,3920.06 4335,4460 4335,4582.53 4352.16,4599.69 U27.4@4396.1,4599.69 ; v1(5620,5090) 5620,5095 5750.31,5225.31 U28.4@5851.75,5225.31
  Top Layer w10: U27.4@4396.1,4599.69 4435.31,4599.69 v1(4445,4590) ; v1(5710,4545) 5714.25,4549.25 U1.21@5774.88,4549.25
  Bottom Layer w8: v1(5620,5090) 5620,5040 5865,4795 5865,4705 5710,4550 v1(5710,4545)
  Bottom Layer w10: v1(4445,4590) 4490,4545 v1(5710,4545)
INFRARED-RAY: H5.2 U1.22 | length 1462.2
  Top Layer w8: U1.22@5774.88,4517.76 5777.12,4520 v1(5910,4520)
  Bottom Layer w8: H5.2@5845,3625 5845,3665 5480,4030 5480,4125 5685,4330 5858.95,4330 5910,4381.05 v1(5910,4520)
LED: LED1.1 U1.23 | length 159.8
  Top Layer w10: LED1.1@5680.79,4392.83 5675,4398.62 5675,4425 5736.26,4486.26 U1.23@5774.88,4486.26
LIGHT_ADC: H4.3 U1.7 | length 2291.3
  Top Layer w8: v1(5840,4550) 5840,4595 5885.74,4640.74 6100.9,4640.74 U1.7@6108.9,4648.74
  Bottom Layer w8: H4.3@4405.36,3625 4915,3625 5645,4355 5830,4355 5875,4400 5875,4515 v1(5840,4550)
MOSI: U1.26 U29.1 | length 1189.5
  Top Layer w8: U1.26@5863.15,4397.99 5863.15,4346.85 6320,3890 6685,3890 U29.1@6775,3800
NRST: C7.2 R1.1 SW1.2 U1.6 | length 573.7
  Top Layer w8: R1.1@6374.36,4732.01 6374.36,4749.36 6420,4795 6518.19,4795 SW1.2@6578.98,4734.21
  Top Layer w10: U1.6@6108.9,4612.24 6175.15,4612.24 C7.2@6287.01,4724.1 ; C7.2@6287.01,4734.1 6289.11,4732.01 R1.1@6369.36,4732.01
OSC_IN: C6.1 OSC1.3 U1.2 | length 220.2
  Top Layer w10: U1.2@6108.9,4486.26 6230.85,4486.26 C6.1@6239.75,4477.36 6239.75,4409.46 OSC1.3@6245.63,4403.58 6245.63,4398.31 OSC1.3@6242.68,4401.26
PGND: C1.2 C3.1 C16.1 C20.1 C21.1 C22.1 C23.1 C26.1 C28.1 C29.1 C30.1 C31.1 CN2.1 D7.2 Q3.2 R0.1 R4.1 R12.1 R19.1 R21.2 U26.7 U28.9 | length 248.2
  Top Layer w10: R19.1@5953.52,5374.48 5953.52,5291.48 5980,5265 6036.47,5265 U28.9@6036.79,5264.69
  Top Layer w20: v1(5360,4755) 5372.04,4742.96 U26.7@5425.85,4742.96
  other v1: 4705,5151.11 4705,5187.42 4705,5220 4736.24,5220 4770,5220 4803.85,5220 5430,5345 5470,5345 5510,5345 5550,5345 5430,5385 5470,5385 5510,5385 5550,5385 5430,5425 5470,5425 5510,5425 5550,5425 5430,5465 5470,5465 5510,5465 5550,5465
POWER: R15.2 U1.17 | length 1639.9
  Top Layer w10: v1(4370,5005) 4417.8,5005 R15.2@4419.46,5003.34 ; U1.17@5774.88,4675.24 5774.88,4714.88 v1(5775,4715)
  Bottom Layer w10: v1(4370,5005) 4690,4685 5735,4685 5765,4715 v1(5775,4715)
RADER: U1.3 U3.1 | length 1354.7
  Top Layer w8: U3.1@5370,3720 5370,3740 5655,4025 6015,4025 6050,4060 v1(6050,4095) ; v1(6045,4515) 6106.14,4515 U1.3@6108.9,4517.76
  Bottom Layer w8: v1(6045,4515) 6050,4510 v1(6050,4095)
RADER_RX: U1.1 U3.2 | length 1290
  Top Layer w8: U3.2@5370,3670 5381.31,3670 5701.31,3990 6030,3990 6090,4050 v1(6090,4070) ; v1(6090,4385) 6108.9,4403.9 U1.1@6108.9,4454.76
  Bottom Layer w8: v1(6090,4070) v1(6090,4385)
RADER_TX: U1.12 U3.3 | length 1563
  Top Layer w8: U3.3@5370,3620 5320,3620 5295,3645 5295,3875 v1(5535,4115) ; U1.12@5957.64,4732.01 5957.64,4667.36 v1(5960,4665)
  Bottom Layer w8: v1(5535,4115) 5535,4125 5710,4300 5905,4300 5960,4355 v1(5960,4665)
SPI_CS: U1.20 U26.1 | length 207.7
  Top Layer w10: U26.1@5644.15,4692.96 5644.15,4640.85 5704.25,4580.75 U1.20@5774.88,4580.75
